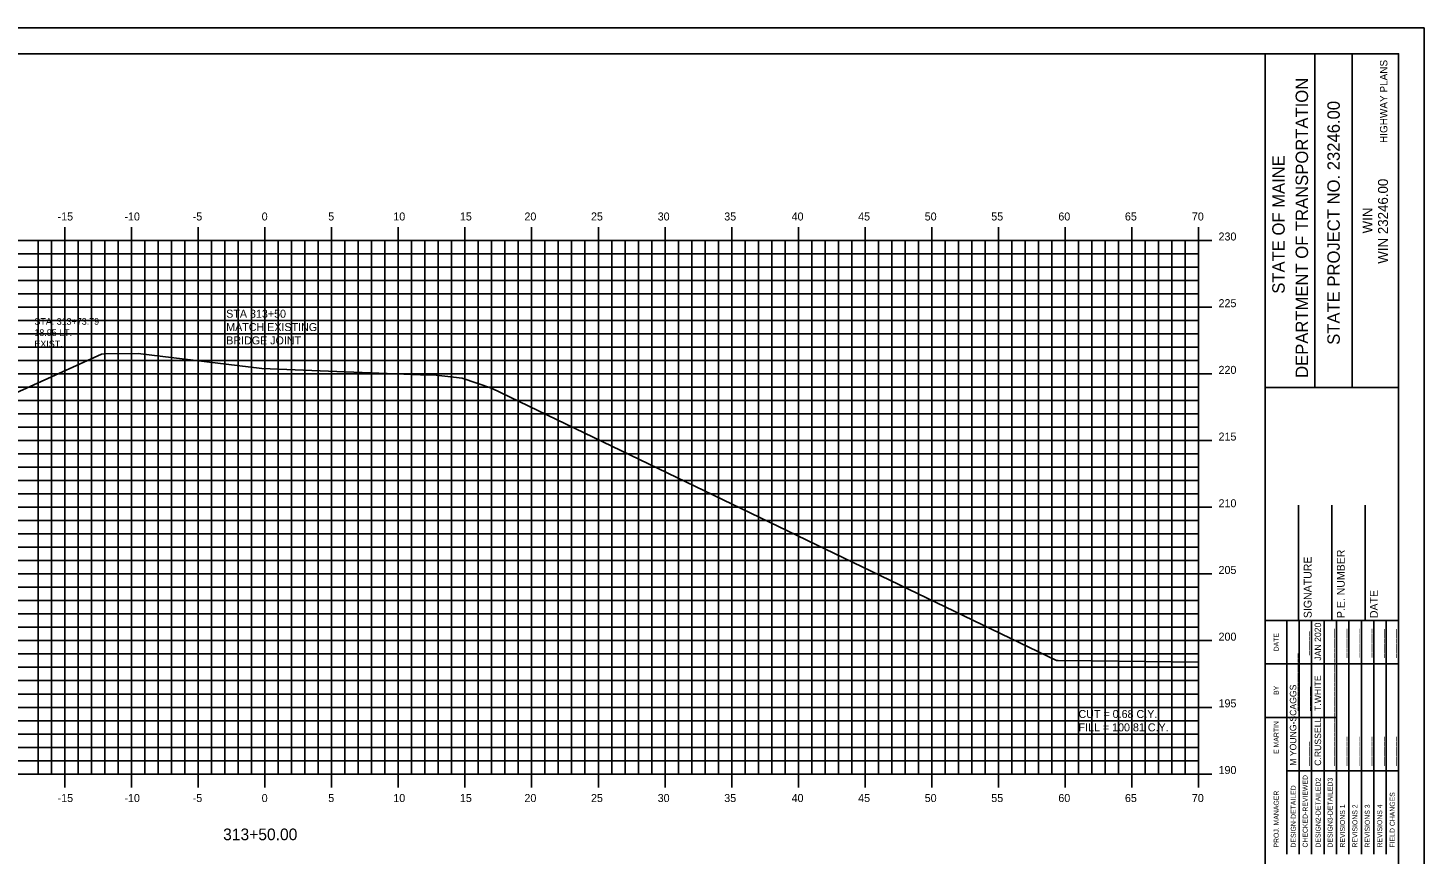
# Model space of a CAD drawing. Extents: x 1138098 to 1138268, y 608981 to 609091.
# Drawn here: x 1138163.2 to 1138267.8, y 609029.3 to 609091.3 of the extents above; entities that cross this region are included whole.
import ezdxf

# ---------------------------------------------------------------- set-up
doc = ezdxf.new("R2010")
doc.units = 0
for name, color, linetype in [('ANNOTATION', 7, 'Continuous'), ('BORDER', 7, 'Continuous'), ('D_Text_Monospaced', 7, 'Continuous'), ('D_Text_Standard', 7, 'Continuous'), ('H_V ANNOTATION', 7, 'Continuous'), ('HIGHWAY_TITLE', 7, 'Continuous'), ('MAJOR', 7, 'Continuous'), ('MINOR', 7, 'Continuous'), ('PLOT BOUNDARY', 7, 'Continuous'), ('S_Roadway_Centerline', 7, 'Continuous')]:
    doc.layers.add(name, color=color, linetype=linetype)

msp = doc.modelspace()

# ---------------------------------------------------------------- linework, layer by layer
at = {"layer": 'BORDER'}
for p, q in [((1138255.92, 608984.34), (1138255.92, 609089.34)), ((1138259.65, 609064.33), (1138259.65, 609089.33)), ((1138262.45, 609064.33), (1138262.45, 609089.33)), ((1138255.92, 609064.33), (1138265.92, 609064.33)), ((1138258.42, 609046.84), (1138258.42, 609055.49)), ((1138260.92, 609046.84), (1138260.92, 609055.49)), ((1138263.42, 609046.84), (1138263.42, 609055.49)), ((1138255.92, 609046.84), (1138265.92, 609046.84))]:
    msp.add_line(p, q, dxfattribs=at)
msp.add_lwpolyline([(1138105.92, 608984.34), (1138265.92, 608984.34), (1138265.92, 609089.34), (1138105.92, 609089.34)], close=True, dxfattribs=at)
for points in [[(1138257.54, 609043.59), (1138257.54, 609046.84)], [(1138257.54, 609029.34), (1138257.54, 609046.13)], [(1138258.47, 609029.34), (1138258.47, 609046.84)], [(1138259.4, 609046.84), (1138259.4, 609029.34)], [(1138260.33, 609029.34), (1138260.33, 609046.84)], [(1138261.27, 609029.34), (1138261.27, 609046.84)], [(1138262.2, 609029.34), (1138262.2, 609046.84)], [(1138263.13, 609029.34), (1138263.13, 609046.84)], [(1138264.06, 609029.34), (1138264.06, 609046.84)], [(1138264.99, 609029.34), (1138264.99, 609046.84)], [(1138255.92, 609043.59), (1138265.92, 609043.59)], [(1138255.92, 609039.59), (1138257.54, 609039.59)], [(1138257.54, 609039.59), (1138261.26, 609039.59)], [(1138257.54, 609035.59), (1138265.92, 609035.59)]]:
    msp.add_lwpolyline(points, dxfattribs=at)
at = {"layer": 'MAJOR'}
for p, q in [((1138165.92, 609076.34), (1138165.92, 609075.34)), ((1138170.92, 609076.34), (1138170.92, 609075.34)), ((1138175.92, 609076.34), (1138175.92, 609075.34)), ((1138180.92, 609076.34), (1138180.92, 609075.34)), ((1138185.92, 609076.34), (1138185.92, 609075.34)), ((1138190.92, 609076.34), (1138190.92, 609075.34)), ((1138195.92, 609076.34), (1138195.92, 609075.34)), ((1138200.92, 609076.34), (1138200.92, 609075.34)), ((1138205.92, 609076.34), (1138205.92, 609075.34)), ((1138210.92, 609076.34), (1138210.92, 609075.34)), ((1138215.92, 609076.34), (1138215.92, 609075.34)), ((1138220.92, 609076.34), (1138220.92, 609075.34)), ((1138225.92, 609076.34), (1138225.92, 609075.34)), ((1138230.92, 609076.34), (1138230.92, 609075.34)), ((1138235.92, 609076.34), (1138235.92, 609075.34)), ((1138240.92, 609076.34), (1138240.92, 609075.34)), ((1138245.92, 609076.34), (1138245.92, 609075.34)), ((1138250.92, 609076.34), (1138250.92, 609075.34)), ((1138110.92, 609075.34), (1138250.92, 609075.34)), ((1138110.92, 609075.34), (1138250.92, 609075.34)), ((1138165.92, 609035.34), (1138165.92, 609075.34)), ((1138170.92, 609035.34), (1138170.92, 609075.34)), ((1138175.92, 609035.34), (1138175.92, 609075.34)), ((1138180.92, 609035.34), (1138180.92, 609075.34)), ((1138185.92, 609035.34), (1138185.92, 609075.34)), ((1138190.92, 609035.34), (1138190.92, 609075.34)), ((1138195.92, 609035.34), (1138195.92, 609075.34)), ((1138200.92, 609035.34), (1138200.92, 609075.34)), ((1138205.92, 609035.34), (1138205.92, 609075.34)), ((1138210.92, 609035.34), (1138210.92, 609075.34)), ((1138215.92, 609035.34), (1138215.92, 609075.34)), ((1138220.92, 609035.34), (1138220.92, 609075.34)), ((1138225.92, 609035.34), (1138225.92, 609075.34)), ((1138230.92, 609035.34), (1138230.92, 609075.34)), ((1138235.92, 609035.34), (1138235.92, 609075.34)), ((1138240.92, 609035.34), (1138240.92, 609075.34)), ((1138245.92, 609035.34), (1138245.92, 609075.34)), ((1138251.92, 609075.34), (1138249.92, 609075.34)), ((1138250.92, 609035.34), (1138250.92, 609075.34)), ((1138250.92, 609035.34), (1138250.92, 609075.34)), ((1138110.92, 609070.34), (1138250.92, 609070.34)), ((1138251.92, 609070.34), (1138249.92, 609070.34)), ((1138110.92, 609065.34), (1138250.92, 609065.34)), ((1138251.92, 609065.34), (1138249.92, 609065.34)), ((1138110.92, 609060.34), (1138250.92, 609060.34)), ((1138251.92, 609060.34), (1138249.92, 609060.34)), ((1138110.92, 609055.34), (1138250.92, 609055.34)), ((1138251.92, 609055.34), (1138249.92, 609055.34)), ((1138110.92, 609050.34), (1138250.92, 609050.34)), ((1138251.92, 609050.34), (1138249.92, 609050.34)), ((1138110.92, 609045.34), (1138250.92, 609045.34)), ((1138251.92, 609045.34), (1138249.92, 609045.34)), ((1138110.92, 609040.34), (1138250.92, 609040.34)), ((1138251.92, 609040.34), (1138249.92, 609040.34)), ((1138110.92, 609035.34), (1138250.92, 609035.34)), ((1138110.92, 609035.34), (1138250.92, 609035.34)), ((1138165.92, 609034.33), (1138165.92, 609035.34)), ((1138170.92, 609034.33), (1138170.92, 609035.34)), ((1138175.92, 609034.33), (1138175.92, 609035.34)), ((1138180.92, 609034.33), (1138180.92, 609035.34)), ((1138185.92, 609034.33), (1138185.92, 609035.34)), ((1138190.92, 609034.33), (1138190.92, 609035.34)), ((1138195.92, 609034.33), (1138195.92, 609035.34)), ((1138200.92, 609034.33), (1138200.92, 609035.34)), ((1138205.92, 609034.33), (1138205.92, 609035.34)), ((1138210.92, 609034.33), (1138210.92, 609035.34)), ((1138215.92, 609034.33), (1138215.92, 609035.34)), ((1138220.92, 609034.33), (1138220.92, 609035.34)), ((1138225.92, 609034.33), (1138225.92, 609035.34)), ((1138230.92, 609034.33), (1138230.92, 609035.34)), ((1138235.92, 609034.33), (1138235.92, 609035.34)), ((1138240.92, 609034.33), (1138240.92, 609035.34)), ((1138245.92, 609034.33), (1138245.92, 609035.34)), ((1138251.92, 609035.34), (1138249.92, 609035.34)), ((1138250.92, 609034.33), (1138250.92, 609035.34))]:
    msp.add_line(p, q, dxfattribs=at)
at = {"layer": 'MINOR'}
for p, q in [((1138163.92, 609035.34), (1138163.92, 609075.34)), ((1138164.92, 609035.34), (1138164.92, 609075.34)), ((1138166.92, 609035.34), (1138166.92, 609075.34)), ((1138167.92, 609035.34), (1138167.92, 609075.34)), ((1138168.92, 609035.34), (1138168.92, 609075.34)), ((1138169.92, 609035.34), (1138169.92, 609075.34)), ((1138171.92, 609035.34), (1138171.92, 609075.34)), ((1138172.92, 609035.34), (1138172.92, 609075.34)), ((1138173.92, 609035.34), (1138173.92, 609075.34)), ((1138174.92, 609035.34), (1138174.92, 609075.34)), ((1138176.92, 609035.34), (1138176.92, 609075.34)), ((1138177.92, 609035.34), (1138177.92, 609075.34)), ((1138178.92, 609035.34), (1138178.92, 609075.34)), ((1138179.92, 609035.34), (1138179.92, 609075.34)), ((1138181.92, 609035.34), (1138181.92, 609075.34)), ((1138182.92, 609035.34), (1138182.92, 609075.34)), ((1138183.92, 609035.34), (1138183.92, 609075.34)), ((1138184.92, 609035.34), (1138184.92, 609075.34)), ((1138186.92, 609035.34), (1138186.92, 609075.34)), ((1138187.92, 609035.34), (1138187.92, 609075.34)), ((1138188.92, 609035.34), (1138188.92, 609075.34)), ((1138189.92, 609035.34), (1138189.92, 609075.34)), ((1138191.92, 609035.34), (1138191.92, 609075.34)), ((1138192.92, 609035.34), (1138192.92, 609075.34)), ((1138193.92, 609035.34), (1138193.92, 609075.34)), ((1138194.92, 609035.34), (1138194.92, 609075.34)), ((1138196.92, 609035.34), (1138196.92, 609075.34)), ((1138197.92, 609035.34), (1138197.92, 609075.34)), ((1138198.92, 609035.34), (1138198.92, 609075.34)), ((1138199.92, 609035.34), (1138199.92, 609075.34)), ((1138201.92, 609035.34), (1138201.92, 609075.34)), ((1138202.92, 609035.34), (1138202.92, 609075.34)), ((1138203.92, 609035.34), (1138203.92, 609075.34)), ((1138204.92, 609035.34), (1138204.92, 609075.34)), ((1138206.92, 609035.34), (1138206.92, 609075.34)), ((1138207.92, 609035.34), (1138207.92, 609075.34)), ((1138208.92, 609035.34), (1138208.92, 609075.34)), ((1138209.92, 609035.34), (1138209.92, 609075.34)), ((1138211.92, 609035.34), (1138211.92, 609075.34)), ((1138212.92, 609035.34), (1138212.92, 609075.34)), ((1138213.92, 609035.34), (1138213.92, 609075.34)), ((1138214.92, 609035.34), (1138214.92, 609075.34)), ((1138216.92, 609035.34), (1138216.92, 609075.34)), ((1138217.92, 609035.34), (1138217.92, 609075.34)), ((1138218.92, 609035.34), (1138218.92, 609075.34)), ((1138219.92, 609035.34), (1138219.92, 609075.34)), ((1138221.92, 609035.34), (1138221.92, 609075.34)), ((1138222.92, 609035.34), (1138222.92, 609075.34)), ((1138223.92, 609035.34), (1138223.92, 609075.34)), ((1138224.92, 609035.34), (1138224.92, 609075.34)), ((1138226.92, 609035.34), (1138226.92, 609075.34)), ((1138227.92, 609035.34), (1138227.92, 609075.34)), ((1138228.92, 609035.34), (1138228.92, 609075.34)), ((1138229.92, 609035.34), (1138229.92, 609075.34)), ((1138231.92, 609035.34), (1138231.92, 609075.34)), ((1138232.92, 609035.34), (1138232.92, 609075.34)), ((1138233.92, 609035.34), (1138233.92, 609075.34)), ((1138234.92, 609035.34), (1138234.92, 609075.34)), ((1138236.92, 609035.34), (1138236.92, 609075.34)), ((1138237.92, 609035.34), (1138237.92, 609075.34)), ((1138238.92, 609035.34), (1138238.92, 609075.34)), ((1138239.92, 609035.34), (1138239.92, 609075.34)), ((1138241.92, 609035.34), (1138241.92, 609075.34)), ((1138242.92, 609035.34), (1138242.92, 609075.34)), ((1138243.92, 609035.34), (1138243.92, 609075.34)), ((1138244.92, 609035.34), (1138244.92, 609075.34)), ((1138246.92, 609035.34), (1138246.92, 609075.34)), ((1138247.92, 609035.34), (1138247.92, 609075.34)), ((1138248.92, 609035.34), (1138248.92, 609075.34)), ((1138249.92, 609035.34), (1138249.92, 609075.34)), ((1138110.92, 609074.34), (1138250.92, 609074.34)), ((1138250.92, 609074.34), (1138249.92, 609074.34)), ((1138110.92, 609073.34), (1138250.92, 609073.34)), ((1138250.92, 609073.34), (1138249.92, 609073.34)), ((1138110.92, 609072.34), (1138250.92, 609072.34)), ((1138250.92, 609072.34), (1138249.92, 609072.34)), ((1138110.92, 609071.34), (1138250.92, 609071.34)), ((1138250.92, 609071.34), (1138249.92, 609071.34)), ((1138110.92, 609069.34), (1138250.92, 609069.34)), ((1138250.92, 609069.34), (1138249.92, 609069.34)), ((1138110.92, 609068.34), (1138250.92, 609068.34)), ((1138250.92, 609068.34), (1138249.92, 609068.34)), ((1138110.92, 609067.34), (1138250.92, 609067.34)), ((1138250.92, 609067.34), (1138249.92, 609067.34)), ((1138110.92, 609066.34), (1138250.92, 609066.34)), ((1138250.92, 609066.34), (1138249.92, 609066.34)), ((1138110.92, 609064.34), (1138250.92, 609064.34)), ((1138250.92, 609064.34), (1138249.92, 609064.34)), ((1138110.92, 609063.34), (1138250.92, 609063.34)), ((1138250.92, 609063.34), (1138249.92, 609063.34)), ((1138110.92, 609062.34), (1138250.92, 609062.34)), ((1138250.92, 609062.34), (1138249.92, 609062.34)), ((1138110.92, 609061.34), (1138250.92, 609061.34)), ((1138250.92, 609061.34), (1138249.92, 609061.34)), ((1138110.92, 609059.34), (1138250.92, 609059.34)), ((1138250.92, 609059.34), (1138249.92, 609059.34)), ((1138110.92, 609058.34), (1138250.92, 609058.34)), ((1138250.92, 609058.34), (1138249.92, 609058.34)), ((1138110.92, 609057.34), (1138250.92, 609057.34)), ((1138250.92, 609057.34), (1138249.92, 609057.34)), ((1138110.92, 609056.34), (1138250.92, 609056.34)), ((1138250.92, 609056.34), (1138249.92, 609056.34)), ((1138110.92, 609054.34), (1138250.92, 609054.34)), ((1138250.92, 609054.34), (1138249.92, 609054.34)), ((1138110.92, 609053.34), (1138250.92, 609053.34)), ((1138250.92, 609053.34), (1138249.92, 609053.34)), ((1138110.92, 609052.34), (1138250.92, 609052.34)), ((1138250.92, 609052.34), (1138249.92, 609052.34)), ((1138110.92, 609051.34), (1138250.92, 609051.34)), ((1138250.92, 609051.34), (1138249.92, 609051.34)), ((1138110.92, 609049.34), (1138250.92, 609049.34)), ((1138250.92, 609049.34), (1138249.92, 609049.34)), ((1138110.92, 609048.34), (1138250.92, 609048.34)), ((1138250.92, 609048.34), (1138249.92, 609048.34)), ((1138110.92, 609047.34), (1138250.92, 609047.34)), ((1138250.92, 609047.34), (1138249.92, 609047.34)), ((1138110.92, 609046.34), (1138250.92, 609046.34)), ((1138250.92, 609046.34), (1138249.92, 609046.34)), ((1138110.92, 609044.34), (1138250.92, 609044.34)), ((1138250.92, 609044.34), (1138249.92, 609044.34)), ((1138110.92, 609043.34), (1138250.92, 609043.34)), ((1138250.92, 609043.34), (1138249.92, 609043.34)), ((1138110.92, 609042.34), (1138250.92, 609042.34)), ((1138250.92, 609042.34), (1138249.92, 609042.34)), ((1138110.92, 609041.34), (1138250.92, 609041.34)), ((1138250.92, 609041.34), (1138249.92, 609041.34)), ((1138110.92, 609039.34), (1138250.92, 609039.34)), ((1138250.92, 609039.34), (1138249.92, 609039.34)), ((1138110.92, 609038.34), (1138250.92, 609038.34)), ((1138250.92, 609038.34), (1138249.92, 609038.34)), ((1138110.92, 609037.34), (1138250.92, 609037.34)), ((1138250.92, 609037.34), (1138249.92, 609037.34)), ((1138110.92, 609036.34), (1138250.92, 609036.34)), ((1138250.92, 609036.34), (1138249.92, 609036.34))]:
    msp.add_line(p, q, dxfattribs=at)
at = {"layer": 'PLOT BOUNDARY'}
msp.add_lwpolyline([(1138097.83, 608981.28), (1138267.83, 608981.28), (1138267.83, 609091.28), (1138097.83, 609091.28)], close=True, dxfattribs=at)
at = {"layer": 'S_Roadway_Centerline'}
msp.add_lwpolyline([(1138110.92, 609043.36), (1138118.56, 609043.32), (1138133.12, 609050.73), (1138168.66, 609066.82), (1138168.66, 609066.82), (1138168.66, 609066.82), (1138168.86, 609066.84), (1138171.43, 609066.88), (1138180.68, 609065.74), (1138192.58, 609065.28), (1138193.76, 609065.25), (1138195.72, 609065.03), (1138197.91, 609064.27), (1138240.27, 609043.85), (1138240.39, 609043.84), (1138242.92, 609043.82), (1138250.92, 609043.73)], dxfattribs=at)

# ---------------------------------------------------------------- texts
at = {"layer": 'ANNOTATION'}
for s, p in [('STA 313+50', (1138178.02, 609069.55)), ('MATCH EXISTING', (1138178.02, 609068.55)), ('BRIDGE JOINT', (1138178.02, 609067.55))]:
    msp.add_text(s, height=0.6, dxfattribs=at).set_placement(p)
at = {"layer": 'BORDER'}
for s, height, p in [('DEPARTMENT OF TRANSPORTATION', 0.9318, (1138259.13, 609065.04)), ('STATE PROJECT NO. 23246.00', 0.9318, (1138261.51, 609067.52)), ('STATE OF MAINE', 0.9318, (1138257.38, 609071.35)), ('WIN 23246.00', 0.7453, (1138265.12, 609073.6)), ('WIN', 0.745, (1138263.96, 609075.87)), ('SIGNATURE', 0.591, (1138259.4, 609047.03)), ('P.E. NUMBER', 0.5906, (1138261.88, 609047.03)), ('DATE', 0.591, (1138264.36, 609047.03)), ('_____', 0.485, (1138259.14, 609044.24)), ('JAN 2020', 0.485, (1138260.11, 609043.84)), ('______', 0.485, (1138261, 609044.06)), ('______', 0.485, (1138261.94, 609044.06)), ('______', 0.485, (1138262.87, 609044.07)), ('______', 0.485, (1138263.8, 609044.07)), ('______', 0.485, (1138264.73, 609044.04)), ('______', 0.485, (1138265.66, 609044.04)), ('DATE', 0.371, (1138256.93, 609044.54)), ('____________', 0.4845, (1138258.25, 609040.07)), ('____________', 0.4845, (1138261, 609040.07)), ('BY', 0.371, (1138256.93, 609041.27)), ('M YOUNG-SCAGGS', 0.4845, (1138258.25, 609035.96)), ('_____', 0.485, (1138259.18, 609040.07)), ('T.WHITE', 0.485, (1138260.11, 609040.07)), ('____________', 0.4845, (1138261, 609035.96)), ('E MARTIN', 0.373, (1138256.93, 609036.85)), ('C.RUSSELL', 0.485, (1138260.11, 609035.96)), ('_____', 0.485, (1138259.14, 609035.96)), ('______', 0.485, (1138261.94, 609035.96)), ('______', 0.485, (1138262.87, 609035.96)), ('______', 0.485, (1138263.8, 609035.96)), ('______', 0.485, (1138264.73, 609035.96)), ('______', 0.485, (1138265.66, 609035.96)), ('CHECKED-REVIEWED', 0.3727, (1138259.1, 609029.83)), ('DESIGN2-DETAILED2', 0.3727, (1138260.07, 609029.83)), ('DESIGN3-DETAILED3', 0.3727, (1138260.97, 609029.83)), ('PROJ. MANAGER', 0.3727, (1138256.93, 609029.83)), ('DESIGN-DETAILED', 0.3727, (1138258.21, 609029.83)), ('FIELD CHANGES', 0.3727, (1138265.63, 609029.83)), ('REVISIONS 1', 0.3727, (1138261.9, 609029.83)), ('REVISIONS 2', 0.3727, (1138262.83, 609029.83)), ('REVISIONS 3', 0.3727, (1138263.76, 609029.83)), ('REVISIONS 4', 0.3727, (1138264.69, 609029.83))]:
    msp.add_text(s, height=height, rotation=90, dxfattribs=at).set_placement(p)
at = {"layer": 'D_Text_Monospaced'}
for s, p in [('STA. 313+73.79', (1138163.64, 609069.02)), ('18.95 LT.', (1138163.64, 609068.18)), ('EXIST. ', (1138163.64, 609067.34))]:
    msp.add_text(s, height=0.5, dxfattribs=at).set_placement(p)
at = {"layer": 'D_Text_Standard'}
for s, p in [('CUT = 0.68 C.Y.', (1138241.92, 609039.54)), ('FILL = 100.81 C.Y.', (1138241.92, 609038.54))]:
    msp.add_text(s, height=0.6, dxfattribs=at).set_placement(p)
at = {"layer": 'H_V ANNOTATION'}
for s, height, p in [('-15', 0.6, (1138165.38, 609076.84)), ('-10', 0.6, (1138170.39, 609076.84)), ('-5', 0.6, (1138175.51, 609076.84)), ('0', 0.6, (1138180.68, 609076.84)), ('5', 0.6, (1138185.67, 609076.84)), ('10', 0.6, (1138190.55, 609076.84)), ('15', 0.6, (1138195.54, 609076.84)), ('20', 0.6, (1138200.38, 609076.84)), ('25', 0.6, (1138205.37, 609076.84)), ('30', 0.6, (1138210.37, 609076.84)), ('35', 0.6, (1138215.36, 609076.84)), ('40', 0.6, (1138220.41, 609076.84)), ('45', 0.6, (1138225.4, 609076.84)), ('50', 0.6, (1138230.39, 609076.84)), ('55', 0.6, (1138235.38, 609076.84)), ('60', 0.6, (1138240.41, 609076.84)), ('65', 0.6, (1138245.4, 609076.84)), ('70', 0.6, (1138250.42, 609076.84)), ('230', 0.6, (1138252.42, 609075.34)), ('225', 0.6, (1138252.42, 609070.34)), ('220', 0.6, (1138252.42, 609065.34)), ('215', 0.6, (1138252.42, 609060.34)), ('210', 0.6, (1138252.42, 609055.34)), ('205', 0.6, (1138252.42, 609050.34)), ('200', 0.6, (1138252.42, 609045.34)), ('195', 0.6, (1138252.42, 609040.34)), ('190', 0.6, (1138252.42, 609035.34)), ('-15', 0.6, (1138165.38, 609033.24)), ('-10', 0.6, (1138170.39, 609033.24)), ('-5', 0.6, (1138175.51, 609033.24)), ('0', 0.6, (1138180.68, 609033.24)), ('5', 0.6, (1138185.67, 609033.24)), ('10', 0.6, (1138190.55, 609033.24)), ('15', 0.6, (1138195.54, 609033.24)), ('20', 0.6, (1138200.38, 609033.24)), ('25', 0.6, (1138205.37, 609033.24)), ('30', 0.6, (1138210.37, 609033.24)), ('35', 0.6, (1138215.36, 609033.24)), ('40', 0.6, (1138220.41, 609033.24)), ('45', 0.6, (1138225.4, 609033.24)), ('50', 0.6, (1138230.39, 609033.24)), ('55', 0.6, (1138235.38, 609033.24)), ('60', 0.6, (1138240.41, 609033.24)), ('65', 0.6, (1138245.4, 609033.24)), ('70', 0.6, (1138250.42, 609033.24)), ('313+50.00', 0.875, (1138177.79, 609030.38))]:
    msp.add_text(s, height=height, dxfattribs=at).set_placement(p)
at = {"layer": 'HIGHWAY_TITLE'}
msp.add_text('HIGHWAY PLANS', height=0.559, rotation=90, dxfattribs=at).set_placement((1138265.08, 609082.65))

doc.saveas('drawing.dxf')
